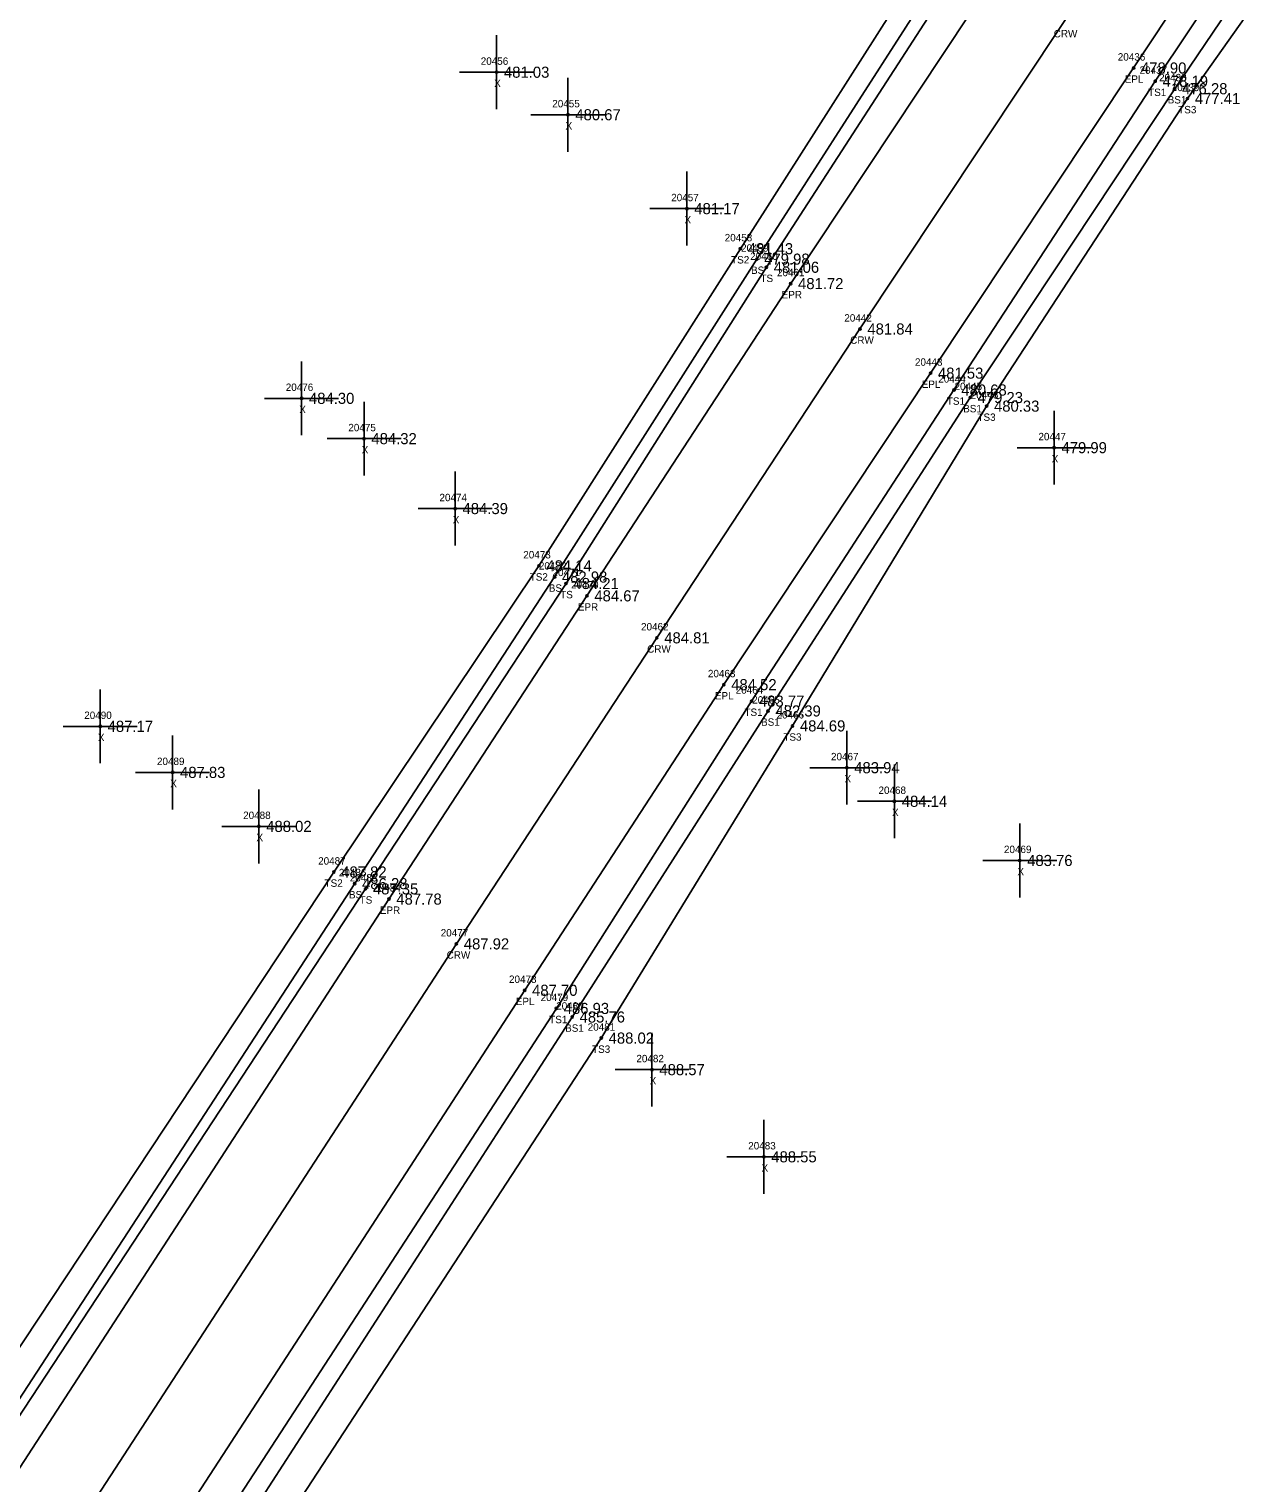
# Model space of a CAD drawing. Extents: x 1741010 to 1742139, y 749382 to 750625.
# Drawn here: x 1741324.2 to 1741488.5, y 749679.2 to 749875.8 of the extents above; entities that cross this region are included whole.
import ezdxf

# ---------------------------------------------------------------- set-up
doc = ezdxf.new("R2010")
doc.units = 0
for name, color, linetype in [('RD_DTM_BkLn1', 7, 'Continuous'), ('RD_DTM_BkLn2', 7, 'Continuous'), ('RD_DTM_BkLn_txCode', 7, 'Continuous'), ('RD_EX_Misc', 7, 'Continuous'), ('RD_EX_Misc_txCode', 7, 'Continuous'), ('RD_EX_Road', 7, 'Continuous'), ('RD_EX_Road_txCode', 7, 'Continuous'), ('RD_EX_TX_Misc_ELEV', 7, 'Continuous'), ('RD_EX_TX_Road_ELEV', 7, 'Continuous'), ('RD_HC_Survey_ELEV', 7, 'Continuous'), ('RD_HC_Survey_txCode', 7, 'Continuous'), ('RD_SMD_Locator', 7, 'Continuous')]:
    doc.layers.add(name, color=color, linetype=linetype)

msp = doc.modelspace()

# ---------------------------------------------------------------- linework, layer by layer
at = {"layer": 'RD_DTM_BkLn1'}
msp.add_lwpolyline([(1741583.42, 750045.09), (1741578.78, 750039.19), (1741548.6, 749999.46), (1741519.68, 749959.35), (1741491.7, 749918.15), (1741464.01, 749876.67), (1741436.51, 749835.23), (1741409.05, 749793.46), (1741381.95, 749752.07), (1741327.4, 749668.12), (1741273.18, 749584.75), (1741218.51, 749501.3), (1741163.8, 749416.96)], dxfattribs=at)
at = {"layer": 'RD_DTM_BkLn2'}
for points in [[(1741595, 750038.14), (1741574.61, 750056.92), (1741567.17, 750063.05), (1741557.5, 750056.24), (1741528.84, 750013.89), (1741502.42, 749971.51), (1741486.02, 749940.89), (1741477.71, 749927.84), (1741450.78, 749885.21), (1741423.85, 749843.58), (1741396.77, 749800.81), (1741369.66, 749759.51), (1741314.64, 749675.74), (1741265.52, 749598.52), (1741262.68, 749595.73), (1741260.89, 749596.52)], [(1741553.69, 750058.21), (1741524.69, 750017.65), (1741497.38, 749974.6), (1741482.49, 749941.95), (1741475.22, 749929.78), (1741449.41, 749886.55), (1741422.56, 749844.68), (1741395.22, 749801.69), (1741368.2, 749760.22), (1741313.51, 749676.19), (1741261.6, 749597.61)], [(1741595, 750038.14), (1741592, 750028.61), (1741562.19, 749990.08), (1741531.32, 749949.92), (1741504.18, 749910.32), (1741476.42, 749868.74), (1741449.21, 749826.98), (1741421.85, 749784.9), (1741395.46, 749743.34), (1741340.74, 749659.13), (1741287.12, 749574.46), (1741231.7, 749491.89), (1741176.84, 749408.86)], [(1741599.45, 750031.16), (1741593.66, 750027.37), (1741564.55, 749987.86), (1741532.82, 749948.93), (1741506.71, 749908.62), (1741479.05, 749867.73), (1741451.41, 749825.96), (1741424.08, 749783.57), (1741397.6, 749742.18), (1741343.11, 749657.77), (1741289.87, 749573.19), (1741234.86, 749489.33), (1741179.61, 749406.64)], [(1741602.3, 750028.04), (1741596.22, 750024.37), (1741565.72, 749986.92), (1741536.13, 749947.45), (1741509.05, 749906.34), (1741480.78, 749866.4), (1741453.63, 749824.8), (1741427.39, 749781.55), (1741401.53, 749739.33), (1741346.85, 749655.57), (1741291.93, 749571.65), (1741238.4, 749487.04), (1741181.74, 749404.39)], [(1741479.58, 749943.23), (1741473.48, 749931.03), (1741447.1, 749888.04), (1741420.34, 749846.09), (1741393.11, 749803.2), (1741365.38, 749761.79), (1741310.15, 749678.29), (1741258.88, 749601.42), (1741259.49, 749597.6), (1741260.89, 749596.52)]]:
    msp.add_lwpolyline(points, dxfattribs=at)
at = {"layer": 'RD_EX_Misc'}
for p, q in [((1741387.38, 749864.96), (1741387.38, 749874.96)), ((1741382.38, 749869.96), (1741392.38, 749869.96)), ((1741397.03, 749859.21), (1741397.03, 749869.21)), ((1741392.03, 749864.21), (1741402.03, 749864.21)), ((1741413.11, 749846.51), (1741413.11, 749856.51)), ((1741408.11, 749851.51), (1741418.11, 749851.51)), ((1741361.02, 749820.85), (1741361.02, 749830.85)), ((1741356.02, 749825.85), (1741366.02, 749825.85)), ((1741369.46, 749815.4), (1741369.46, 749825.4)), ((1741462.75, 749814.18), (1741462.75, 749824.18)), ((1741364.46, 749820.4), (1741374.46, 749820.4)), ((1741457.75, 749819.18), (1741467.75, 749819.18)), ((1741381.78, 749805.94), (1741381.78, 749815.94)), ((1741376.78, 749810.94), (1741386.78, 749810.94)), ((1741333.8, 749776.49), (1741333.8, 749786.49)), ((1741328.8, 749781.49), (1741338.8, 749781.49)), ((1741343.59, 749770.26), (1741343.59, 749780.26)), ((1741434.73, 749770.9), (1741434.73, 749780.9)), ((1741429.73, 749775.9), (1741439.73, 749775.9)), ((1741441.16, 749766.35), (1741441.16, 749776.35)), ((1741338.59, 749775.26), (1741348.59, 749775.26)), ((1741355.24, 749762.96), (1741355.24, 749772.96)), ((1741436.16, 749771.35), (1741446.16, 749771.35)), ((1741350.24, 749767.96), (1741360.24, 749767.96)), ((1741458.11, 749758.35), (1741458.11, 749768.35)), ((1741453.11, 749763.35), (1741463.11, 749763.35)), ((1741408.39, 749730.06), (1741408.39, 749740.06)), ((1741403.39, 749735.06), (1741413.39, 749735.06)), ((1741423.52, 749718.27), (1741423.52, 749728.27)), ((1741418.52, 749723.27), (1741428.52, 749723.27))]:
    msp.add_line(p, q, dxfattribs=at)
at = {"layer": 'RD_EX_Road'}
for points in [[(1741574.14, 750053.03), (1741573.09, 750050.35), (1741570.35, 750045.84), (1741539.87, 750005.43), (1741510.87, 749966.19), (1741482.97, 749924.75), (1741454.76, 749883.01), (1741427.14, 749841.37), (1741399.6, 749799.14), (1741372.83, 749758.13), (1741317.93, 749673.6), (1741267.39, 749595.97), (1741263.6, 749591.05), (1741254, 749576.22), (1741209.28, 749507.22), (1741154.74, 749422.71)], [(1741592.65, 750037.91), (1741590.39, 750035.78), (1741587.68, 750032.32), (1741557.76, 749993.29), (1741528.74, 749952.66), (1741501.16, 749912.21), (1741473.5, 749870.53), (1741446.05, 749829.26), (1741418.1, 749787.13), (1741391.18, 749745.79), (1741336.54, 749661.65), (1741282.05, 749578.36), (1741227.71, 749494.6), (1741173.28, 749411)]]:
    msp.add_lwpolyline(points, dxfattribs=at)
at = {"layer": 'RD_SMD_Locator'}
for centre in [(1741387.38, 749869.96), (1741473.5, 749870.53), (1741476.42, 749868.74), (1741479.05, 749867.73), (1741480.78, 749866.4), (1741397.03, 749864.21), (1741413.11, 749851.51), (1741420.34, 749846.09), (1741422.56, 749844.68), (1741423.85, 749843.58), (1741427.14, 749841.37), (1741436.51, 749835.23), (1741446.05, 749829.26), (1741449.21, 749826.98), (1741361.02, 749825.85), (1741451.41, 749825.96), (1741453.63, 749824.8), (1741369.46, 749820.4), (1741462.75, 749819.18), (1741381.78, 749810.94), (1741393.11, 749803.2), (1741395.22, 749801.69), (1741396.77, 749800.81), (1741399.6, 749799.14), (1741409.05, 749793.46), (1741418.1, 749787.13), (1741421.85, 749784.9), (1741424.08, 749783.57), (1741333.8, 749781.49), (1741427.39, 749781.55), (1741434.73, 749775.9), (1741343.59, 749775.26), (1741441.16, 749771.35), (1741355.24, 749767.96), (1741365.38, 749761.79), (1741458.11, 749763.35), (1741368.2, 749760.22), (1741369.66, 749759.51), (1741372.83, 749758.13), (1741381.95, 749752.07), (1741391.18, 749745.79), (1741395.46, 749743.34), (1741397.6, 749742.18), (1741401.53, 749739.33), (1741408.39, 749735.06), (1741423.52, 749723.27)]:
    msp.add_circle(centre, 0.15, dxfattribs=at)

# ---------------------------------------------------------------- texts
at = {"layer": 'RD_DTM_BkLn_txCode'}
for s, p in [('20437', (1741474.3, 749869.74)), ('20438', (1741476.94, 749868.73)), ('20439', (1741478.66, 749867.4)), ('TS1', (1741475.46, 749866.74)), ('BS1', (1741478.11, 749865.73)), ('TS3', (1741479.53, 749864.4)), ('20458', (1741418.22, 749847.09)), ('20459', (1741420.44, 749845.68)), ('TS2', (1741419.09, 749844.09)), ('20460', (1741421.67, 749844.58)), ('BS', (1741421.78, 749842.68)), ('TS', (1741423.05, 749841.58)), ('20444', (1741447.09, 749827.98)), ('20445', (1741449.29, 749826.96)), ('20446', (1741451.49, 749825.8)), ('TS1', (1741448.25, 749824.98)), ('BS1', (1741450.46, 749823.96)), ('TS3', (1741452.39, 749822.8)), ('20473', (1741390.99, 749804.2)), ('20472', (1741393.1, 749802.69)), ('TS2', (1741391.86, 749801.2)), ('20471', (1741394.94, 749801.81)), ('BS', (1741394.44, 749799.69)), ('TS', (1741395.98, 749798.81)), ('20464', (1741419.71, 749785.9)), ('20465', (1741421.94, 749784.57)), ('TS1', (1741420.89, 749782.9)), ('20466', (1741425.23, 749782.55)), ('BS1', (1741423.14, 749781.57)), ('TS3', (1741426.15, 749779.55)), ('20487', (1741363.26, 749762.79)), ('20486', (1741366.06, 749761.22)), ('TS2', (1741364.13, 749759.79)), ('20485', (1741367.54, 749760.51)), ('BS', (1741367.42, 749758.22)), ('TS', (1741368.87, 749757.51)), ('20479', (1741393.34, 749744.34)), ('20480', (1741395.44, 749743.18)), ('TS1', (1741394.5, 749741.34)), ('BS1', (1741396.65, 749740.18)), ('20481', (1741399.7, 749740.33)), ('TS3', (1741400.29, 749737.33))]:
    msp.add_text(s, height=1, dxfattribs=at).set_placement(p)
at = {"layer": 'RD_EX_Misc_txCode'}
for s, p in [('20456', (1741385.24, 749870.96)), ('X', (1741387.06, 749867.96)), ('20455', (1741394.91, 749865.21)), ('X', (1741396.71, 749862.21)), ('20457', (1741410.99, 749852.51)), ('X', (1741412.79, 749849.51)), ('20476', (1741358.88, 749826.85)), ('X', (1741360.71, 749823.85)), ('20475', (1741367.34, 749821.4)), ('20447', (1741460.63, 749820.18)), ('X', (1741369.15, 749818.4)), ('X', (1741462.43, 749817.18)), ('20474', (1741379.66, 749811.94)), ('X', (1741381.46, 749808.94)), ('20490', (1741331.64, 749782.49)), ('X', (1741333.48, 749779.49)), ('20467', (1741432.59, 749776.9)), ('20489', (1741341.47, 749776.26)), ('X', (1741343.27, 749773.26)), ('X', (1741434.42, 749773.9)), ('20468', (1741439.01, 749772.35)), ('20488', (1741353.12, 749768.96)), ('X', (1741440.84, 749769.35)), ('X', (1741354.92, 749765.96)), ('20469', (1741455.97, 749764.35)), ('X', (1741457.8, 749761.35)), ('20482', (1741406.28, 749736.06)), ('X', (1741408.08, 749733.06)), ('20483', (1741421.4, 749724.27)), ('X', (1741423.2, 749721.27))]:
    msp.add_text(s, height=1, dxfattribs=at).set_placement(p)
at = {"layer": 'RD_EX_Road_txCode'}
for s, p in [('20436', (1741471.36, 749871.53)), ('EPL', (1741472.3, 749868.53)), ('20461', (1741425.29, 749842.37)), ('EPR', (1741425.92, 749839.37)), ('20443', (1741443.94, 749830.26)), ('EPL', (1741444.85, 749827.26)), ('20470', (1741397.45, 749800.14)), ('EPR', (1741398.37, 749797.14)), ('20463', (1741415.95, 749788.13)), ('EPL', (1741416.89, 749785.13)), ('20484', (1741370.71, 749759.13)), ('EPR', (1741371.6, 749756.13)), ('20478', (1741389.06, 749746.79)), ('EPL', (1741389.98, 749743.79))]:
    msp.add_text(s, height=1, dxfattribs=at).set_placement(p)
at = {"layer": 'RD_EX_TX_Misc_ELEV'}
for s, p in [('481.03', (1741388.38, 749869.21)), ('478.19', (1741477.42, 749867.99)), ('476.28', (1741480.05, 749866.98)), ('477.41', (1741481.78, 749865.65)), ('480.67', (1741398.03, 749863.46)), ('481.17', (1741414.11, 749850.76)), ('481.43', (1741421.34, 749845.34)), ('479.98', (1741423.56, 749843.93)), ('481.06', (1741424.85, 749842.83)), ('484.30', (1741362.02, 749825.1)), ('480.68', (1741450.21, 749826.23)), ('479.23', (1741452.41, 749825.21)), ('480.33', (1741454.63, 749824.05)), ('484.32', (1741370.46, 749819.65)), ('479.99', (1741463.75, 749818.43)), ('484.39', (1741382.78, 749810.19)), ('484.14', (1741394.11, 749802.45)), ('482.98', (1741396.22, 749800.94)), ('484.21', (1741397.77, 749800.06)), ('483.77', (1741422.85, 749784.15)), ('482.39', (1741425.08, 749782.82)), ('487.17', (1741334.8, 749780.74)), ('484.69', (1741428.39, 749780.8)), ('487.83', (1741344.59, 749774.51)), ('483.94', (1741435.73, 749775.15)), ('484.14', (1741442.16, 749770.6)), ('488.02', (1741356.24, 749767.21)), ('483.76', (1741459.11, 749762.6)), ('487.82', (1741366.38, 749761.04)), ('486.28', (1741369.2, 749759.47)), ('487.35', (1741370.66, 749758.76)), ('486.93', (1741396.46, 749742.59)), ('485.76', (1741398.6, 749741.43)), ('488.02', (1741402.53, 749738.58)), ('488.57', (1741409.39, 749734.31)), ('488.55', (1741424.52, 749722.52))]:
    msp.add_text(s, height=1.5, dxfattribs=at).set_placement(p)
at = {"layer": 'RD_EX_TX_Road_ELEV'}
for s, p in [('478.90', (1741474.5, 749869.78)), ('481.72', (1741428.14, 749840.62)), ('481.53', (1741447.05, 749828.51)), ('484.67', (1741400.6, 749798.39)), ('484.52', (1741419.1, 749786.38)), ('487.78', (1741373.83, 749757.38)), ('487.70', (1741392.18, 749745.04))]:
    msp.add_text(s, height=1.5, dxfattribs=at).set_placement(p)
at = {"layer": 'RD_HC_Survey_ELEV'}
for s, p in [('481.84', (1741437.51, 749834.48)), ('484.81', (1741410.05, 749792.71)), ('487.92', (1741382.95, 749751.32))]:
    msp.add_text(s, height=1.5, dxfattribs=at).set_placement(p)
at = {"layer": 'RD_HC_Survey_txCode'}
for s, p in [('CRW', (1741462.7, 749874.67)), ('20442', (1741434.39, 749836.23)), ('CRW', (1741435.19, 749833.23)), ('20462', (1741406.91, 749794.46)), ('CRW', (1741407.74, 749791.46)), ('20477', (1741379.83, 749753.07)), ('CRW', (1741380.63, 749750.07))]:
    msp.add_text(s, height=1, dxfattribs=at).set_placement(p)

doc.saveas('drawing.dxf')
